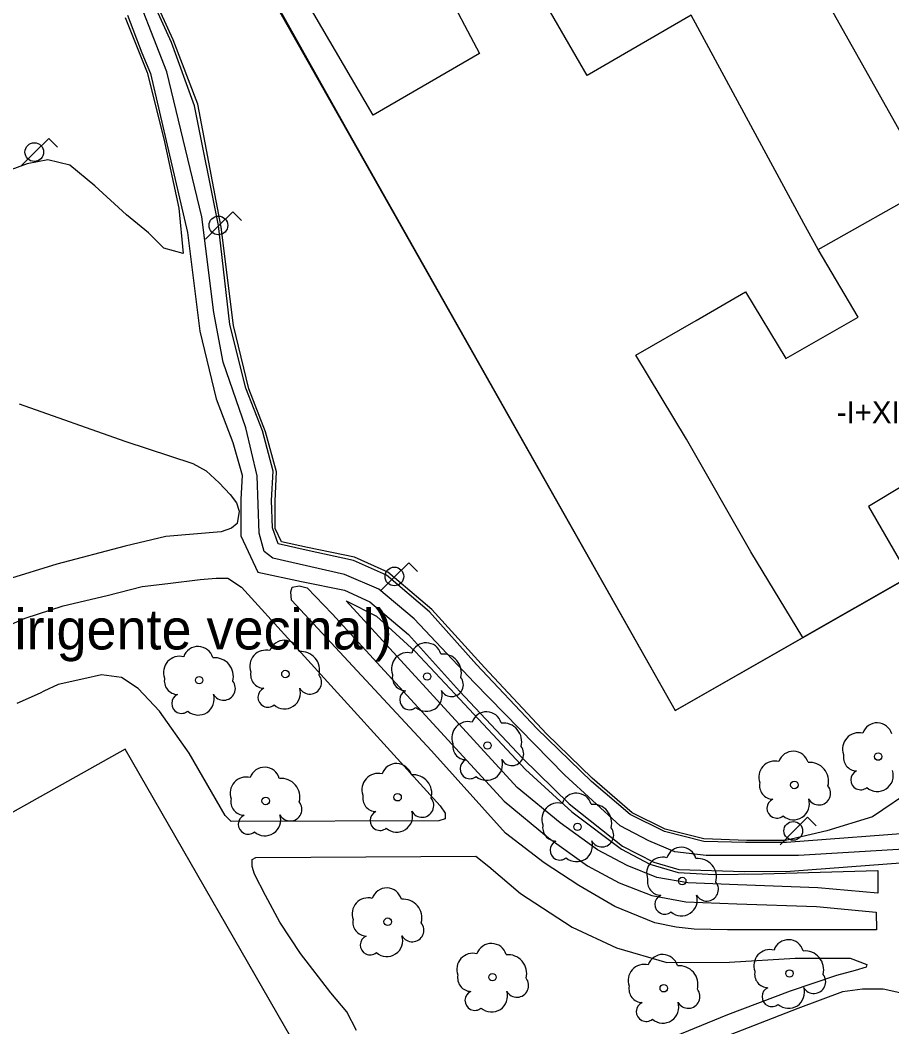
# Model space of a CAD drawing. Extents: x 282771 to 285132, y 4823109 to 4825496.
# Drawn here: x 283506.6 to 283566, y 4823469.1 to 4823537.7 of the extents above; entities that cross this region are included whole.
import ezdxf

# ---------------------------------------------------------------- set-up
doc = ezdxf.new("R2010")
doc.units = 0
for name, color, linetype in [('ARBOL', 7, 'Continuous'), ('CARRIL-BICI-AREA', 7, 'Continuous'), ('CARRIL-BICI-EJE', 7, 'Continuous'), ('EDIFICIO', 7, 'Continuous'), ('FAROLA', 7, 'Continuous'), ('MEDIANERA', 7, 'Continuous'), ('PARQUE-JARDIN-AREA', 7, 'Continuous'), ('PARQUE-JARDIN-TEXTO', 7, 'Continuous'), ('TXT-ALTURA-EDIFICIO', 7, 'Continuous'), ('VALLA', 7, 'Continuous'), ('ZONA-VERDE', 7, 'Continuous')]:
    doc.layers.add(name, color=color, linetype=linetype)

msp = doc.modelspace()

# ---------------------------------------------------------------- linework, layer by layer
at = {"layer": 'ARBOL'}
for centre in [(283518.792, 4823492.72), (283524.67, 4823493.14), (283534.327, 4823492.972), (283538.441, 4823488.269), (283565.061, 4823487.514), (283559.35, 4823485.582), (283523.326, 4823484.491), (283532.311, 4823484.743), (283544.571, 4823482.727), (283551.709, 4823479.033), (283531.64, 4823476.261), (283538.777, 4823472.483), (283559.015, 4823472.735), (283550.449, 4823471.727)]:
    msp.add_circle(centre, 0.255, dxfattribs=at)
for centre, radius, start, end in [((283518.722, 4823493.98), 1.038, 15.64225, 161.38431), ((283524.6, 4823494.4), 1.038, 15.64225, 161.38431), ((283534.257, 4823494.232), 1.038, 15.64225, 161.38431), ((283517.462, 4823493.25), 1.097, 75.43176, 200.55605), ((283523.34, 4823493.67), 1.097, 75.43176, 200.55605), ((283525.73, 4823493.4), 1.272, 345.0327, 95.79922), ((283532.997, 4823493.502), 1.097, 75.43176, 200.55605), ((283535.387, 4823493.232), 1.272, 345.0327, 95.79922), ((283519.852, 4823492.98), 1.272, 345.0327, 95.79922), ((283523.23, 4823493.1), 0.935, 168.59894, 268.13232), ((283526.34, 4823492.57), 0.797, 208.96243, 38.99099), ((283532.887, 4823492.932), 0.935, 168.59894, 268.13232), ((283517.352, 4823492.68), 0.935, 168.59894, 268.13232), ((283520.462, 4823492.15), 0.797, 208.96243, 38.99099), ((283535.997, 4823492.402), 0.797, 208.96243, 38.99099), ((283517.592, 4823491.13), 0.672, 113.73669, 309.47246), ((283518.732, 4823491.43), 1.086, 228.95444, 17.92792), ((283523.47, 4823491.55), 0.672, 113.73669, 309.47246), ((283524.61, 4823491.85), 1.086, 228.95444, 17.92792), ((283533.127, 4823491.382), 0.672, 113.73669, 309.47246), ((283534.267, 4823491.682), 1.086, 228.95444, 17.92792), ((283538.371, 4823489.529), 1.038, 15.64225, 161.38431), ((283537.111, 4823488.799), 1.097, 75.43176, 200.55605), ((283539.501, 4823488.529), 1.272, 345.0327, 95.79922), ((283564.991, 4823488.774), 1.038, 15.64225, 161.38431), ((283563.731, 4823488.044), 1.097, 75.43176, 200.55605), ((283537.001, 4823488.229), 0.935, 168.59894, 268.13232), ((283540.111, 4823487.699), 0.797, 208.96243, 38.99099), ((283559.28, 4823486.842), 1.038, 15.64225, 161.38431), ((283563.621, 4823487.474), 0.935, 168.59894, 268.13232), ((283523.256, 4823485.751), 1.038, 15.64225, 161.38431), ((283532.241, 4823486.003), 1.038, 15.64225, 161.38431), ((283537.241, 4823486.679), 0.672, 113.73669, 309.47246), ((283538.381, 4823486.979), 1.086, 228.95444, 17.92792), ((283558.02, 4823486.112), 1.097, 75.43176, 200.55605), ((283560.41, 4823485.842), 1.272, 345.0327, 95.79922), ((283521.996, 4823485.021), 1.097, 75.43176, 200.55605), ((283530.981, 4823485.273), 1.097, 75.43176, 200.55605), ((283533.371, 4823485.003), 1.272, 345.0327, 95.79922), ((283563.861, 4823485.924), 0.672, 113.73669, 309.47246), ((283565.001, 4823486.224), 1.086, 228.95444, 17.92792), ((283524.386, 4823484.751), 1.272, 345.0327, 95.79922), ((283557.91, 4823485.542), 0.935, 168.59894, 268.13232), ((283561.02, 4823485.012), 0.797, 208.96243, 38.99099), ((283530.871, 4823484.703), 0.935, 168.59894, 268.13232), ((283544.501, 4823483.987), 1.038, 15.64225, 161.38431), ((283521.886, 4823484.451), 0.935, 168.59894, 268.13232), ((283524.996, 4823483.921), 0.797, 208.96243, 38.99099), ((283533.981, 4823484.173), 0.797, 208.96243, 38.99099), ((283543.241, 4823483.257), 1.097, 75.43176, 200.55605), ((283545.631, 4823482.987), 1.272, 345.0327, 95.79922), ((283558.15, 4823483.992), 0.672, 113.73669, 309.47246), ((283559.29, 4823484.292), 1.086, 228.95444, 17.92792), ((283522.126, 4823482.901), 0.672, 113.73669, 309.47246), ((283523.266, 4823483.201), 1.086, 228.95444, 17.92792), ((283531.111, 4823483.153), 0.672, 113.73669, 309.47246), ((283532.251, 4823483.453), 1.086, 228.95444, 17.92792), ((283543.131, 4823482.687), 0.935, 168.59894, 268.13232), ((283546.241, 4823482.157), 0.797, 208.96243, 38.99099), ((283543.371, 4823481.137), 0.672, 113.73669, 309.47246), ((283544.511, 4823481.437), 1.086, 228.95444, 17.92792), ((283551.639, 4823480.293), 1.038, 15.64225, 161.38431), ((283550.379, 4823479.563), 1.097, 75.43176, 200.55605), ((283552.769, 4823479.293), 1.272, 345.0327, 95.79922), ((283531.57, 4823477.521), 1.038, 15.64225, 161.38431), ((283550.269, 4823478.993), 0.935, 168.59894, 268.13232), ((283553.379, 4823478.463), 0.797, 208.96243, 38.99099), ((283530.31, 4823476.791), 1.097, 75.43176, 200.55605), ((283550.509, 4823477.443), 0.672, 113.73669, 309.47246), ((283551.649, 4823477.743), 1.086, 228.95444, 17.92792), ((283532.7, 4823476.521), 1.272, 345.0327, 95.79922), ((283530.2, 4823476.221), 0.935, 168.59894, 268.13232), ((283533.31, 4823475.691), 0.797, 208.96243, 38.99099), ((283530.44, 4823474.671), 0.672, 113.73669, 309.47246), ((283531.58, 4823474.971), 1.086, 228.95444, 17.92792), ((283538.707, 4823473.743), 1.038, 15.64225, 161.38431), ((283558.945, 4823473.995), 1.038, 15.64225, 161.38431), ((283537.447, 4823473.013), 1.097, 75.43176, 200.55605), ((283539.837, 4823472.743), 1.272, 345.0327, 95.79922), ((283550.379, 4823472.987), 1.038, 15.64225, 161.38431), ((283557.685, 4823473.265), 1.097, 75.43176, 200.55605), ((283560.075, 4823472.995), 1.272, 345.0327, 95.79922), ((283549.119, 4823472.257), 1.097, 75.43176, 200.55605), ((283551.509, 4823471.987), 1.272, 345.0327, 95.79922), ((283537.337, 4823472.443), 0.935, 168.59894, 268.13232), ((283540.447, 4823471.913), 0.797, 208.96243, 38.99099), ((283557.575, 4823472.695), 0.935, 168.59894, 268.13232), ((283560.685, 4823472.165), 0.797, 208.96243, 38.99099), ((283549.009, 4823471.687), 0.935, 168.59894, 268.13232), ((283557.815, 4823471.145), 0.672, 113.73669, 309.47246), ((283558.955, 4823471.445), 1.086, 228.95444, 17.92792), ((283537.577, 4823470.893), 0.672, 113.73669, 309.47246), ((283538.717, 4823471.193), 1.086, 228.95444, 17.92792), ((283552.119, 4823471.157), 0.797, 208.96243, 38.99099), ((283549.249, 4823470.137), 0.672, 113.73669, 309.47246), ((283550.389, 4823470.437), 1.086, 228.95444, 17.92792)]:
    msp.add_arc(centre, radius, start, end, dxfattribs=at)
at = {"layer": 'CARRIL-BICI-AREA'}
for points in [[(283568.411, 4823482.382), (283558.802, 4823481.66), (283556.02, 4823481.651), (283553.172, 4823481.733), (283550.502, 4823482.406), (283548.157, 4823483.558), (283545.536, 4823485.822), (283541.795, 4823489.433), (283537.697, 4823493.783), (283534.484, 4823497.378), (283531.554, 4823499.869), (283529.298, 4823500.867), (283526.093, 4823501.589), (283524.186, 4823502.011), (283523.78, 4823503.113), (283523.715, 4823504.971), (283523.829, 4823506.962), (283523.107, 4823509.712), (283521.963, 4823512.629), (283520.875, 4823516.948), (283520.104, 4823523.709), (283518.473, 4823531.865), (283516.899, 4823536.182), (283514.757, 4823540.952)], [(283513.913, 4823538.049), (283514.879, 4823535.461), (283515.471, 4823534.073), (283517.995, 4823523.239), (283518.848, 4823516.499), (283519.951, 4823511.884), (283521.095, 4823508.927), (283521.714, 4823506.682), (283521.635, 4823505.031), (283521.635, 4823502.556), (283522.799, 4823500.072), (283525.763, 4823499.448), (283528.699, 4823498.843), (283530.411, 4823498.057), (283533.048, 4823495.831), (283536.529, 4823491.981), (283540.817, 4823487.405), (283544.013, 4823484.303), (283547.629, 4823481.4), (283549.782, 4823480.327), (283551.484, 4823479.826), (283555.955, 4823479.688), (283559.063, 4823479.704), (283566.886, 4823480.296)]]:
    msp.add_lwpolyline(points, dxfattribs=at)
at = {"layer": 'CARRIL-BICI-EJE'}
msp.add_lwpolyline([(283578.162, 4823481.882), (283559.64, 4823480.763), (283553.332, 4823480.773), (283551.212, 4823481.029), (283549.441, 4823481.775), (283547.484, 4823482.8), (283543.71, 4823486.25), (283537.54, 4823492.572), (283533.433, 4823496.906), (283531.036, 4823498.93), (283528.702, 4823499.931), (283523.816, 4823501.036), (283523.23, 4823501.489), (283522.871, 4823502.741), (283522.755, 4823506.655), (283521.963, 4823509.919), (283520.436, 4823514.381), (283519.783, 4823517.784), (283518.983, 4823524.287), (283516.6, 4823534.179), (283514.815, 4823538.721)], dxfattribs=at)
at = {"layer": 'EDIFICIO'}
for points in [[(283554.834, 4823550.949), (283566.044, 4823531.029), (283579.604, 4823506.879), (283572.124, 4823502.599), (283569.424, 4823507.569), (283564.404, 4823504.559), (283567.164, 4823499.759), (283559.914, 4823495.619), (283556.384, 4823501.459), (283551.994, 4823509.139), (283548.544, 4823514.859), (283552.664, 4823517.239), (283556.014, 4823519.189), (283558.774, 4823514.639), (283563.684, 4823517.449), (283560.964, 4823522.059), (283559.994, 4823523.839), (283552.313, 4823538.048), (283545.241, 4823533.929), (283542.724, 4823538.249)], [(283535.414, 4823540.119), (283537.884, 4823535.429), (283530.654, 4823531.229), (283519.614, 4823550.099)]]:
    msp.add_lwpolyline(points, dxfattribs=at)
at = {"layer": 'FAROLA'}
for p, q in [((283508.54, 4823529.638), (283507.6, 4823528.708)), ((283509.13, 4823529.048), (283508.54, 4823529.638)), ((283507.6, 4823528.708), (283506.67, 4823527.768)), ((283521.084, 4823524.639), (283520.144, 4823523.709)), ((283521.674, 4823524.049), (283521.084, 4823524.639)), ((283520.144, 4823523.709), (283519.214, 4823522.769)), ((283533.074, 4823500.719), (283532.134, 4823499.789)), ((283533.664, 4823500.129), (283533.074, 4823500.719)), ((283532.134, 4823499.789), (283531.204, 4823498.849)), ((283560.254, 4823483.38), (283559.314, 4823482.45)), ((283560.844, 4823482.79), (283560.254, 4823483.38)), ((283559.314, 4823482.45), (283558.384, 4823481.51))]:
    msp.add_line(p, q, dxfattribs=at)
for centre in [(283507.56, 4823528.708), (283520.104, 4823523.709), (283532.094, 4823499.789), (283559.274, 4823482.45)]:
    msp.add_circle(centre, 0.637, dxfattribs=at)
at = {"layer": 'MEDIANERA'}
msp.add_lwpolyline([(283560.964, 4823522.059), (283568.629, 4823526.374)], dxfattribs=at)
at = {"layer": 'PARQUE-JARDIN-AREA'}
msp.add_lwpolyline([(283495.951, 4823588.308), (283551.23, 4823490.648), (283579.604, 4823506.879), (283583.027, 4823500.185), (283588.86, 4823505.69), (283590.897, 4823506.845), (283592.653, 4823507.436), (283593.9, 4823507.666), (283595.184, 4823507.751), (283596.477, 4823507.685), (283597.754, 4823507.468), (283598.988, 4823507.105), (283600.708, 4823506.314), (283602.665, 4823504.896), (283603.839, 4823503.651), (283605.003, 4823501.968), (283646.934, 4823428.056), (283615.089, 4823406.438)], dxfattribs=at)
at = {"layer": 'VALLA'}
msp.add_lwpolyline([(283526.094, 4823466.57), (283513.754, 4823488.03), (283469.785, 4823463.38), (283482.295, 4823441.34), (283526.094, 4823466.57)], dxfattribs=at)
at = {"layer": 'ZONA-VERDE'}
for p, q in [((283511.72, 4823560.788), (283528.97, 4823530.048)), ((283517.024, 4823536.356), (283514.954, 4823540.876)), ((283513.747, 4823537.887), (283515.253, 4823534.122)), ((283518.697, 4823531.962), (283517.024, 4823536.356)), ((283515.253, 4823534.122), (283516.382, 4823529.602)), ((283520.297, 4823523.583), (283518.697, 4823531.962)), ((283528.97, 4823530.048), (283551.23, 4823490.648)), ((283516.382, 4823529.602), (283517.417, 4823524.895)), ((283508.478, 4823528.19), (283507.067, 4823527.908)), ((283509.984, 4823527.813), (283508.478, 4823528.19)), ((283507.067, 4823527.908), (283505.279, 4823527.249)), ((283511.677, 4823526.401), (283509.984, 4823527.813)), ((283513.841, 4823524.424), (283511.677, 4823526.401)), ((283517.417, 4823524.895), (283517.699, 4823521.788)), ((283515.347, 4823523.2), (283513.841, 4823524.424)), ((283516.381, 4823522.165), (283515.347, 4823523.2)), ((283521.143, 4823516.899), (283520.297, 4823523.583)), ((283517.699, 4823521.788), (283516.381, 4823522.165)), ((283522.178, 4823512.568), (283521.143, 4823516.899)), ((283523.307, 4823509.649), (283522.178, 4823512.568)), ((283506.52, 4823511.546), (283513.72, 4823509.002)), ((283524.06, 4823506.919), (283523.307, 4823509.649)), ((283513.72, 4823509.002), (283518.367, 4823507.495)), ((283518.367, 4823507.495), (283519.261, 4823506.977)), ((283519.261, 4823506.977), (283520.155, 4823506.177)), ((283523.966, 4823504.942), (283524.06, 4823506.919)), ((283520.155, 4823506.177), (283520.908, 4823505.376)), ((283520.908, 4823505.376), (283521.332, 4823504.811)), ((283521.332, 4823504.811), (283521.52, 4823504.246)), ((283523.966, 4823503.059), (283523.966, 4823504.942)), ((283521.52, 4823504.246), (283521.379, 4823503.398)), ((283521.379, 4823503.398), (283521.002, 4823503.068)), ((283520.296, 4823502.833), (283516.531, 4823502.503)), ((283521.002, 4823503.068), (283520.296, 4823502.833)), ((283524.395, 4823502.142), (283523.966, 4823503.059)), ((283516.531, 4823502.503), (283513.755, 4823501.844)), ((283526.183, 4823501.766), (283524.395, 4823502.142)), ((283513.755, 4823501.844), (283509.096, 4823500.619)), ((283529.382, 4823501.107), (283526.183, 4823501.766)), ((283509.096, 4823500.619), (283505.707, 4823499.583)), ((283531.64, 4823500.071), (283529.382, 4823501.107)), ((283534.651, 4823497.529), (283531.64, 4823500.071)), ((283514.919, 4823499.113), (283516.657, 4823499.3)), ((283516.657, 4823499.3), (283518.865, 4823499.583)), ((283518.865, 4823499.583), (283519.946, 4823499.677)), ((283519.946, 4823499.677), (283520.745, 4823499.677)), ((283520.745, 4823499.677), (283521.685, 4823499.066)), ((283525.127, 4823499.064), (283525.598, 4823499.158)), ((283525.598, 4823499.158), (283526.163, 4823499.017)), ((283559.9, 4823495.598), (283567.15, 4823499.738)), ((283509.516, 4823497.796), (283512.523, 4823498.501)), ((283512.523, 4823498.501), (283514.919, 4823499.113)), ((283521.685, 4823499.066), (283535.216, 4823484.164)), ((283525.033, 4823498.734), (283525.127, 4823499.064)), ((283525.08, 4823498.169), (283525.033, 4823498.734)), ((283526.163, 4823499.017), (283527.849, 4823497.25)), ((283506.932, 4823496.95), (283509.516, 4823497.796)), ((283534.635, 4823487.902), (283525.08, 4823498.169)), ((283540.472, 4823485.406), (283528.799, 4823498.122)), ((283528.799, 4823498.122), (283530.87, 4823497.086)), ((283527.849, 4823497.25), (283539.583, 4823484.468)), ((283530.87, 4823497.086), (283533.506, 4823494.684)), ((283538.226, 4823493.575), (283534.651, 4823497.529)), ((283505.24, 4823496.198), (283506.932, 4823496.95)), ((283551.23, 4823490.648), (283559.9, 4823495.598)), ((283533.506, 4823494.684), (283536.236, 4823491.764)), ((283512.147, 4823493.095), (283510.925, 4823492.813)), ((283513.509, 4823492.907), (283512.147, 4823493.095)), ((283542.46, 4823489.056), (283538.226, 4823493.575)), ((283509.187, 4823492.437), (283508.2, 4823491.967)), ((283510.925, 4823492.813), (283509.187, 4823492.437)), ((283514.637, 4823492.155), (283513.509, 4823492.907)), ((283507.965, 4823491.826), (283506.368, 4823491.121)), ((283508.2, 4823491.967), (283507.965, 4823491.826)), ((283516.093, 4823490.604), (283514.637, 4823492.155)), ((283536.236, 4823491.764), (283541.037, 4823486.631)), ((283518.114, 4823487.736), (283516.093, 4823490.604)), ((283545.565, 4823486.043), (283542.46, 4823489.056)), ((283520.557, 4823483.506), (283518.114, 4823487.736)), ((283539.671, 4823482.298), (283534.635, 4823487.902)), ((283541.037, 4823486.631), (283544.19, 4823483.758)), ((283548.293, 4823483.689), (283545.565, 4823486.043)), ((283567.863, 4823485.572), (283564.664, 4823483.407)), ((283543.39, 4823483.004), (283540.472, 4823485.406)), ((283535.216, 4823484.164), (283535.545, 4823483.647)), ((283539.583, 4823484.468), (283542.602, 4823481.983)), ((283520.98, 4823483.082), (283520.557, 4823483.506)), ((283535.545, 4823483.647), (283535.545, 4823483.271)), ((283544.19, 4823483.758), (283547.579, 4823481.215)), ((283550.551, 4823482.56), (283548.293, 4823483.689)), ((283564.664, 4823483.407), (283561.559, 4823482.465)), ((283535.122, 4823483.13), (283520.98, 4823483.082)), ((283535.545, 4823483.271), (283535.122, 4823483.13)), ((283545.932, 4823481.168), (283543.39, 4823483.004)), ((283542.307, 4823480.273), (283539.671, 4823482.298)), ((283542.602, 4823481.983), (283545.247, 4823480.072)), ((283553.186, 4823481.9), (283550.551, 4823482.56)), ((283561.559, 4823482.465), (283558.737, 4823481.806)), ((283556.102, 4823481.806), (283553.186, 4823481.9)), ((283558.737, 4823481.806), (283556.102, 4823481.806)), ((283522.414, 4823480.497), (283522.649, 4823480.637)), ((283522.649, 4823480.637), (283537.637, 4823480.732)), ((283537.637, 4823480.732), (283538.53, 4823480.027)), ((283547.956, 4823480.085), (283545.932, 4823481.168)), ((283547.579, 4823481.215), (283549.509, 4823480.179)), ((283522.414, 4823480.026), (283522.414, 4823480.497)), ((283522.556, 4823479.509), (283522.414, 4823480.026)), ((283538.53, 4823480.027), (283540.691, 4823478.193)), ((283544.661, 4823478.719), (283542.307, 4823480.273)), ((283545.247, 4823480.072), (283547.413, 4823478.913)), ((283549.98, 4823479.284), (283547.956, 4823480.085)), ((283549.509, 4823480.179), (283551.439, 4823479.614)), ((283523.307, 4823478.052), (283522.556, 4823479.509)), ((283552.098, 4823478.907), (283549.98, 4823479.284)), ((283551.439, 4823479.614), (283553.886, 4823479.473)), ((283553.886, 4823479.473), (283557.181, 4823479.52)), ((283557.181, 4823479.52), (283565.042, 4823479.755)), ((283565.042, 4823479.755), (283565.042, 4823478.201)), ((283547.108, 4823477.306), (283544.661, 4823478.719)), ((283547.413, 4823478.913), (283549.626, 4823478.038)), ((283555.487, 4823478.766), (283552.098, 4823478.907)), ((283560.947, 4823478.578), (283555.487, 4823478.766)), ((283565.042, 4823478.201), (283560.947, 4823478.578)), ((283524.294, 4823476.219), (283523.307, 4823478.052)), ((283540.691, 4823478.193), (283544.215, 4823475.89)), ((283549.626, 4823478.038), (283551.957, 4823477.623)), ((283549.839, 4823476.176), (283547.108, 4823477.306)), ((283551.957, 4823477.623), (283555.438, 4823477.478)), ((283555.438, 4823477.478), (283560.866, 4823477.291)), ((283560.866, 4823477.291), (283564.924, 4823476.917)), ((283564.924, 4823476.917), (283564.948, 4823475.705)), ((283525.703, 4823474.103), (283524.294, 4823476.219)), ((283544.215, 4823475.89), (283547.222, 4823474.48)), ((283551.298, 4823475.893), (283549.839, 4823476.176)), ((283552.521, 4823475.752), (283551.298, 4823475.893)), ((283554.781, 4823475.705), (283552.521, 4823475.752)), ((283561.276, 4823475.705), (283554.781, 4823475.705)), ((283564.948, 4823475.705), (283561.276, 4823475.705)), ((283547.222, 4823474.48), (283550.652, 4823473.492)), ((283527.771, 4823471.424), (283525.703, 4823474.103)), ((283554.927, 4823473.493), (283559.393, 4823473.776)), ((283559.393, 4823473.776), (283563.152, 4823473.776)), ((283563.152, 4823473.776), (283564.279, 4823473.353)), ((283550.652, 4823473.492), (283554.927, 4823473.493)), ((283564.232, 4823473.165), (283563.48, 4823472.93)), ((283564.279, 4823473.353), (283564.232, 4823473.165)), ((283562.212, 4823472.601), (283559.064, 4823471.52)), ((283563.48, 4823472.93), (283562.212, 4823472.601)), ((283528.851, 4823470.108), (283527.771, 4823471.424)), ((283559.064, 4823471.52), (283554.788, 4823469.921)), ((283529.509, 4823468.838), (283528.851, 4823470.108)), ((283554.788, 4823469.921), (283547.318, 4823466.866))]:
    msp.add_line(p, q, dxfattribs=at)
msp.add_lwpolyline([(283566.95, 4823471.33), (283565.4, 4823471.659), (283563.99, 4823471.659), (283562.628, 4823471.471), (283559.574, 4823470.343), (283543.881, 4823464.232), (283539.465, 4823462.21), (283537.586, 4823461.082), (283535.659, 4823459.672), (283533.681, 4823457.879), (283532.318, 4823456.187), (283531.849, 4823455.575), (283531.943, 4823454.776), (283532.412, 4823454.024), (283533.023, 4823453.366), (283533.789, 4823452.595), (283558.784, 4823466.815), (283587.257, 4823415.667)], dxfattribs=at)

# ---------------------------------------------------------------- texts
at = {"layer": 'PARQUE-JARDIN-TEXTO'}
msp.add_text('Parque de Agustín Plaza Santidrián (Dirigente vecinal)', height=2.75, dxfattribs=at).set_placement((283443.049, 4823494.813))
at = {"layer": 'TXT-ALTURA-EDIFICIO'}
msp.add_text('-I+XIV', height=1.5, rotation=0.00004, dxfattribs=at).set_placement((283562.234, 4823510.231))

doc.saveas('drawing.dxf')
